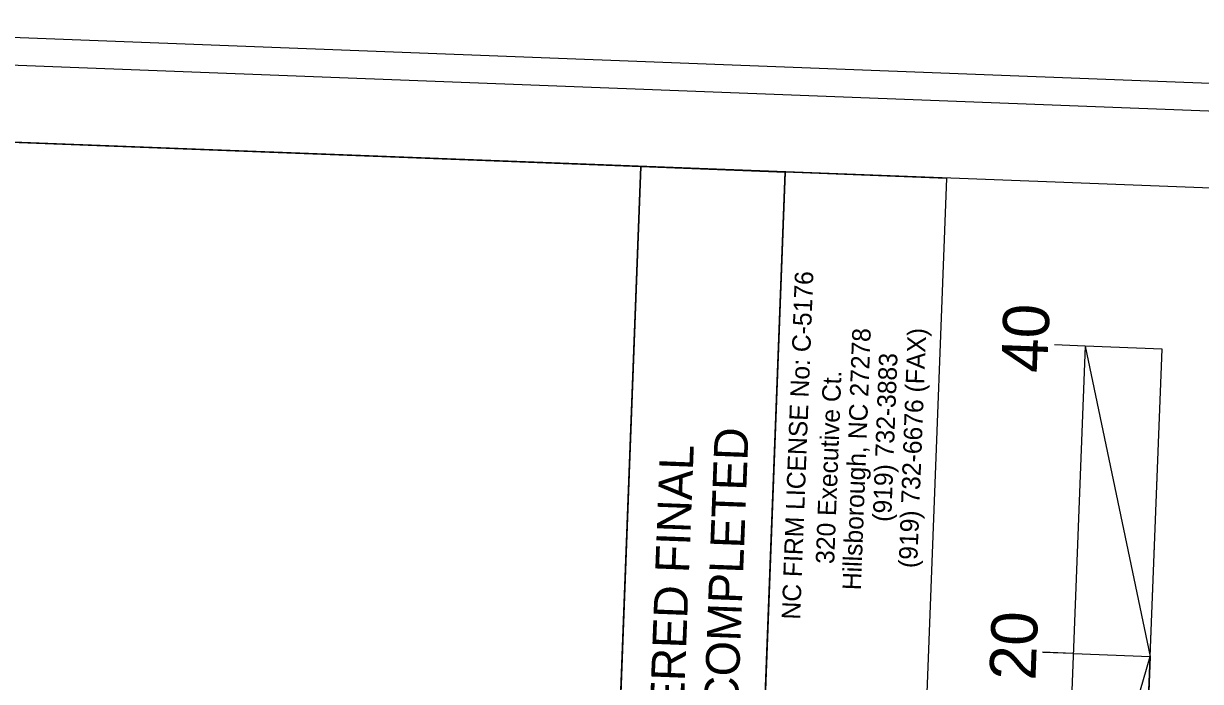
# Model space of a CAD drawing. Extents: x 2097521 to 2097987, y 686521 to 687299.
# Drawn here: x 2097571.8 to 2097648.4, y 687168.4 to 687211.1 of the extents above; entities that cross this region are included whole.
import ezdxf

# ---------------------------------------------------------------- set-up
doc = ezdxf.new("R2010")
doc.units = 0
for name, color, linetype in [('Sheet Block Title CELL', 7, 'Continuous'), ('Sheet Data Field CELL', 7, 'Continuous'), ('Sheet Plot Border Inside CELL', 7, 'Continuous'), ('Sheet Plot Border Outside CELL', 7, 'Continuous'), ('Sheet Profile CELL', 7, 'Continuous'), ('Sheet Sticker Exception Certification CELL', 7, 'Continuous'), ('Sheet Title CELL', 7, 'Continuous')]:
    doc.layers.add(name, color=color, linetype=linetype)

msp = doc.modelspace()

# ---------------------------------------------------------------- linework, layer by layer
at = {"layer": 'Sheet Block Title CELL'}
msp.add_lwpolyline([(2097618.314, 687121.52), (2097621.38, 687201.485), (2097631.875, 687201.082), (2097628.808, 687121.118)], close=True, dxfattribs=at)
at = {"layer": 'Sheet Data Field CELL'}
for p, q in [((2097640.889, 687190.166), (2097638.885, 687190.243)), ((2097640.117, 687170.181), (2097638.124, 687170.257))]:
    msp.add_line(p, q, dxfattribs=at)
at = {"layer": 'Sheet Plot Border Inside CELL'}
msp.add_lwpolyline([(2097952.364, 686526.701), (2097977.91, 687192.812), (2097556.18, 687208.986), (2097530.634, 686542.875)], close=True, dxfattribs=at)
at = {"layer": 'Sheet Plot Border Outside CELL'}
msp.add_lwpolyline([(2097961.138, 686521.161), (2097986.952, 687194.266), (2097547.276, 687211.129), (2097521.461, 686538.023)], close=True, dxfattribs=at)
at = {"layer": 'Sheet Profile CELL'}
for points in [[(2097557.008, 687203.95), (2097534.014, 686604.391), (2097953.705, 686588.295), (2097976.699, 687187.855)], [(2097565.487, 687163.596), (2097567.02, 687203.566), (2097611.987, 687201.842), (2097610.454, 687161.871)]]:
    msp.add_lwpolyline(points, close=True, dxfattribs=at)
at = {"layer": 'Sheet Sticker Exception Certification CELL'}
for p, q in [((2097608.921, 687121.881), (2097611.987, 687201.837)), ((2097611.992, 687201.837), (2097621.385, 687201.476)), ((2097621.38, 687201.477), (2097618.314, 687121.52))]:
    msp.add_line(p, q, dxfattribs=at)
at = {"layer": 'Sheet Title CELL'}
for p, q in [((2097640.889, 687190.161), (2097638.589, 687130.205)), ((2097640.889, 687190.161), (2097638.89, 687190.238)), ((2097645.89, 687189.969), (2097640.889, 687190.161)), ((2097643.586, 687130.013), (2097645.89, 687189.969)), ((2097640.122, 687170.176), (2097638.129, 687170.252)), ((2097640.122, 687170.176), (2097645.119, 687169.984))]:
    msp.add_line(p, q, dxfattribs=at)
for points in [[(2097640.889, 687190.161), (2097645.119, 687169.984), (2097645.89, 687189.969)], [(2097639.361, 687150.19), (2097645.119, 687169.984), (2097644.357, 687149.998)]]:
    msp.add_lwpolyline(points, close=True, dxfattribs=at)

# ---------------------------------------------------------------- texts
at = {"layer": 'Sheet Block Title CELL'}
for s, p in [('NC FIRM LICENSE No: C-5176', (2097622.344, 687172.369)), ('Hillsborough, NC 27278', (2097626.294, 687174.278)), ('(919) 732-6676 (FAX)', (2097629.953, 687175.716)), ('(919) 732-3883', (2097628.266, 687178.722)), ('320 Executive Ct.', (2097624.557, 687175.98))]:
    msp.add_text(s, height=1.20035, rotation=87.8037, dxfattribs=at).set_placement(p)
at = {"layer": 'Sheet Data Field CELL'}
for s, p in [('40', (2097638.414, 687188.387)), ('20', (2097637.652, 687168.401))]:
    msp.add_text(s, height=3, rotation=87.8037, dxfattribs=at).set_placement(p)
at = {"layer": 'Sheet Sticker Exception Certification CELL'}
for s, p in [('UNLESS ALL SIGNATURES COMPLETED', (2097616.818, 687127.982)), ('DOCUMENT NOT CONSIDERED FINAL', (2097613.379, 687130.144))]:
    msp.add_text(s, height=2.2, rotation=87.8037, dxfattribs=at).set_placement(p)

doc.saveas('drawing.dxf')
